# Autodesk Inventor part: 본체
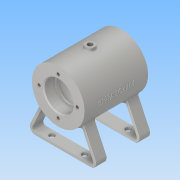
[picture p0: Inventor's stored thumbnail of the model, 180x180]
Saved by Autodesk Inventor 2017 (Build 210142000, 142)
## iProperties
Part Number: 본체
Material: 알루미늄 6061
Document SubType Name: Modeling
Designer: Administrator
Density: 2.7 g/cm^3
Appearance: 알루미늄 - 평지
Mass: 310.363 g
Surface Area: 356.146 cm^2
Volume: 114.949 cm^3
Author: Administrator
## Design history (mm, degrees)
sketch "스케치1"
  geometry: C1 r 29 at (0, 0); 1 further point
  constraints: 1 centre point, 1 coincident
  dimensions: "d0" = 58 diameter of C1
extrude "돌출1" new body sketch "스케치1" stored distance "d1" = 70; taper "d2" = 0 deg
node "작업 평면1"
node "작업 평면2"
sketch "스케치6"
  geometry: C1 r 16 at (0, 0); 1 further point
  constraints: 1 centre point, 1 coincident
  dimensions: "d22" = 32 diameter of C1
extrude "돌출5" cut sketch "스케치6" distance "d23" = 12; taper "d24" = 0 deg
sketch "스케치7"
  geometry: C1 r 14 at (0, 0); 1 further point
  constraints: 1 centre point, 1 coincident
  dimensions: "d25" = 28 diameter of C1
extrude "돌출6" cut sketch "스케치7" distance "d26" = 2; taper "d27" = 0 deg
sketch "스케치8"
  geometry: C1 r 21 at (0, 0); 1 further point
  constraints: 1 centre point, 1 coincident
  dimensions: "d28" = 42 diameter of C1
extrude "돌출7" cut sketch "스케치8" distance "d29" = 42; taper "d30" = 0 deg
sketch "스케치9" dims "d31" = 42
  geometry: 3 further points
  constraints: 2 vertical alignment, 1 coincident, 2 other
hole "구멍1" sketch "스케치9" at (0, 21) diameter "d32" = 3.242; stored, may be unused: countersink angle "d36" = 90 deg, drill point angle "d38" = 118 deg; dims "d33" = 8, "d34" = 4, "d35" = 2, "d37" = 10
node "작업 평면3"
sketch "스케치10"
  geometry: L1 (29, 35)-(-29, 35) reference; C1 r 5 at (0, 0); 1 further point
  constraints: 1 centre point, 1 coincident
  dimensions: "d43" = 10 diameter of C1; "d44" = 35 distance from line of C1.centre L1
extrude "돌출8" join sketch "스케치10" stored distance "d45" = 10; taper "d46" = 0 deg
sketch "스케치13"
  geometry: 1 further point
hole "구멍2" sketch "스케치13" at (0, 0) diameter "d58" = 5.188; stored, may be unused: countersink angle "d62" = 90 deg, drill point angle "d64" = 0 deg; dims "d59" = 6, "d60" = 4, "d61" = 2, "d63" = 8
node "작업 평면5"
  node "작업 평면4"
sketch "스케치14"
  geometry: C1 r 6 at (0, 0); 1 further point
  constraints: 1 centre point, 1 coincident
  dimensions: "d67" = 12 diameter of C1
extrude "돌출11" join sketch "스케치14" stored distance "d68" = 12; taper "d69" = 0 deg
sketch "스케치15"
  geometry: 1 further point
hole "구멍3" sketch "스케치15" at (0, 0) diameter "d70" = 5.188; stored, may be unused: countersink angle "d74" = 90 deg, drill point angle "d76" = 0 deg; dims "d71" = 12, "d72" = 4, "d73" = 2, "d75" = 16
sketch "스케치16"
  geometry: 1 further point
sketch "스케치19"
  geometry: 1 further point
sketch "스케치20"
  geometry: C1 r 1.5 at (0, 0); 1 further point
  constraints: 1 centre point, 1 coincident
  dimensions: "d92" = 3 diameter of C1
extrude "돌출13" cut sketch "스케치20" distance "d93" = 12; taper "d94" = 0 deg
node "작업 평면6"
sketch "스케치22"
  geometry: L1 (-40, -55)-(40, -55); L2 (40, -55)-(22.743, -17.993); L3 (-40, -55)-(-22.743, -17.993); A1 r 29 centre (0, 0) between (22.743, -17.993) and (-22.743, -17.993) reference; 2 further points
  constraints: 6 end point, 2 point on circle, 1 horizontal, 1 midpoint, 1 vertical alignment
  dimensions: "d96" = 55 distance from line of L1 point (0, 0); "d101" = 65 deg angle of L1 L3; "d102" = 65 deg angle of L1 L2; "d103" = 80 distance of L1.start L1.end
extrude "돌출14" join sketch "스케치22" distance "d104" = 12; taper "d105" = 0 deg
sketch "스케치23"
  geometry: L1 (-40, -55)-(-22.743, -17.993) reference; L2 (22.743, -17.993)-(40, -55) reference; L3 (40, -55)-(-40, -55) reference; L4 (20.574, -20.438)-(35.291, -52); L5 (35.291, -52)-(-35.291, -52); L6 (-35.291, -52)-(-20.574, -20.438); C1 r 1.621 at (21, 0) reference; C2 r 1.621 at (0, -21) reference; C3 r 1.621 at (-21, 0) reference; C4 r 1.621 at (0, 21) reference; C5 r 16 at (0, 0) reference; A1 r 29 centre (0, 0) between (-22.743, -17.993) and (22.743, -17.993) reference; A2 r 29 centre (0, 0) between (22.743, -17.993) and (-22.743, -17.993) reference; 1 further point
  constraints: 6 end point, 2 point on circle
  dimensions: "d106" = 3 distance between parallel lines of L2 L4; "d107" = 3 distance between parallel lines of L6 L1; "d108" = 3 distance between parallel lines of L3 L5
extrude "돌출15" cut sketch "스케치23" distance "d109" = 12; taper "d110" = 0 deg
sketch "스케치24"
  geometry: L1 (-4.709, 0)-(75.291, 0) reference; C1 r 3 at (17.291, 6); C2 r 3 at (53.291, 6); 1 further point
  constraints: 2 centre point, 1 horizontal alignment
  dimensions: "d111" = 6 diameter of C2; "d112" = 6 diameter of C1; "d113" = 36 distance of C2.centre C1.centre; "d114" = 18 horizontal distance of C2.centre point (35.291, 30); "d115" = 6 distance from line of L1 C1.centre
extrude "돌출16" cut sketch "스케치24" distance "d116" = 3; taper "d117" = 0 deg
fillet "모깎기1" dims "d118" = 6
fillet "모깎기2" dims "d119" = 1
chamfer "모따기1" distance "d120" = 1; stored, may be unused: second distance "d121" = 2, angle "d122" = 45 deg
fillet "모깎기3" dims "d123" = 3
fillet "모깎기4" dims "d124" = 0.5
fillet "모깎기5" dims "d125" = 3
fillet "모깎기6" dims "d126" = 3
fillet "모깎기7" dims "d127" = 0.3
node "작업 평면7"
sketch "스케치25"
  geometry: L1 (29, -35)-(29, 35) reference; 2 further points
  constraints: 1 coincident, 1 other
  dimensions: "d129" = 29 distance from line of point (0, 0) L1
feature "엠보싱1" sketch "스케치25" dims "d0" = 58, "d130" = 0.5, "d131" = 0
node "솔리드1"
mirror "미러2"
pattern_circular "원형 패턴1" dims angle "d40" = 360 deg
mirror "미러3"
mirror "미러6"
node "절단 모서리 투영3"
other parameters: "d3" = -5, "d6" = -55, "d17" = 3, "d42" = 32, "d65" = -20 deg, "d66" = -32, "d95" = -5, "d128" = 39.25
